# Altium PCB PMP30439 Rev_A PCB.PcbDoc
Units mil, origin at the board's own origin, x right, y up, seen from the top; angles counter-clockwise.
Board outline 2150 x 1400 mil, 2 copper layers (Top Layer, Bottom Layer), stack 62 mil thick; 24 components, 11 nets, 49 pads, 20 vias.
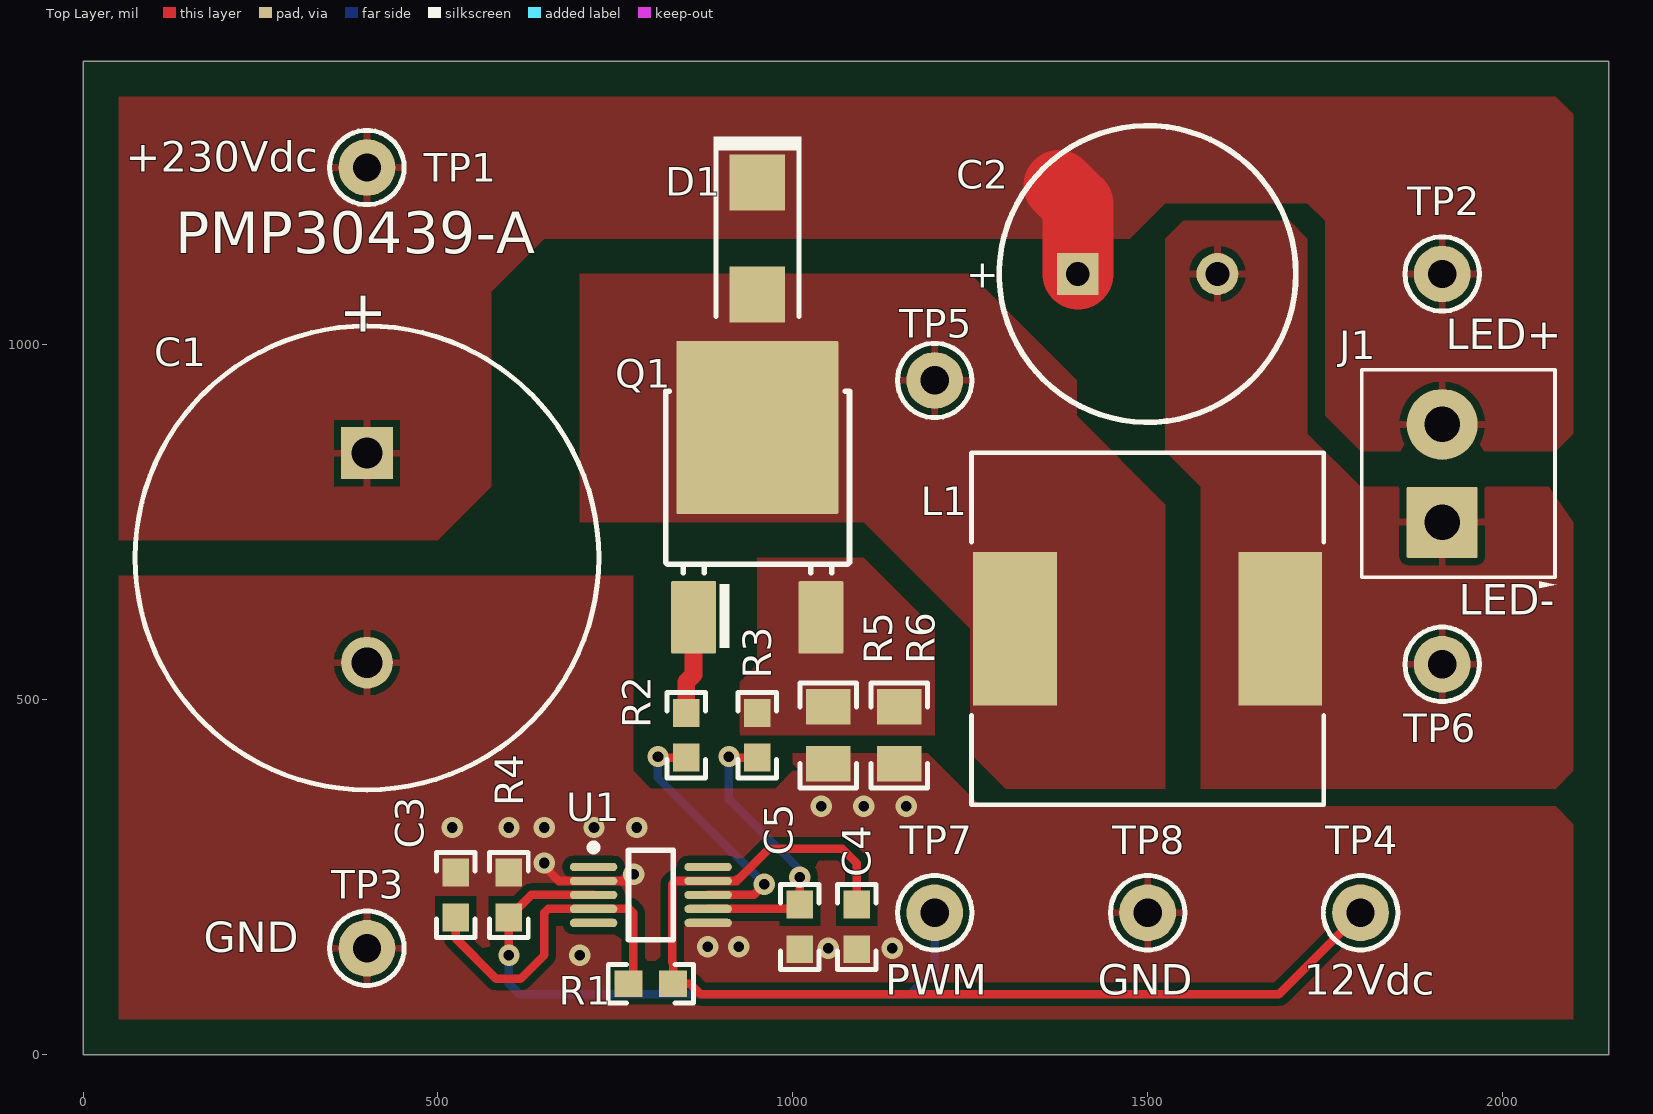
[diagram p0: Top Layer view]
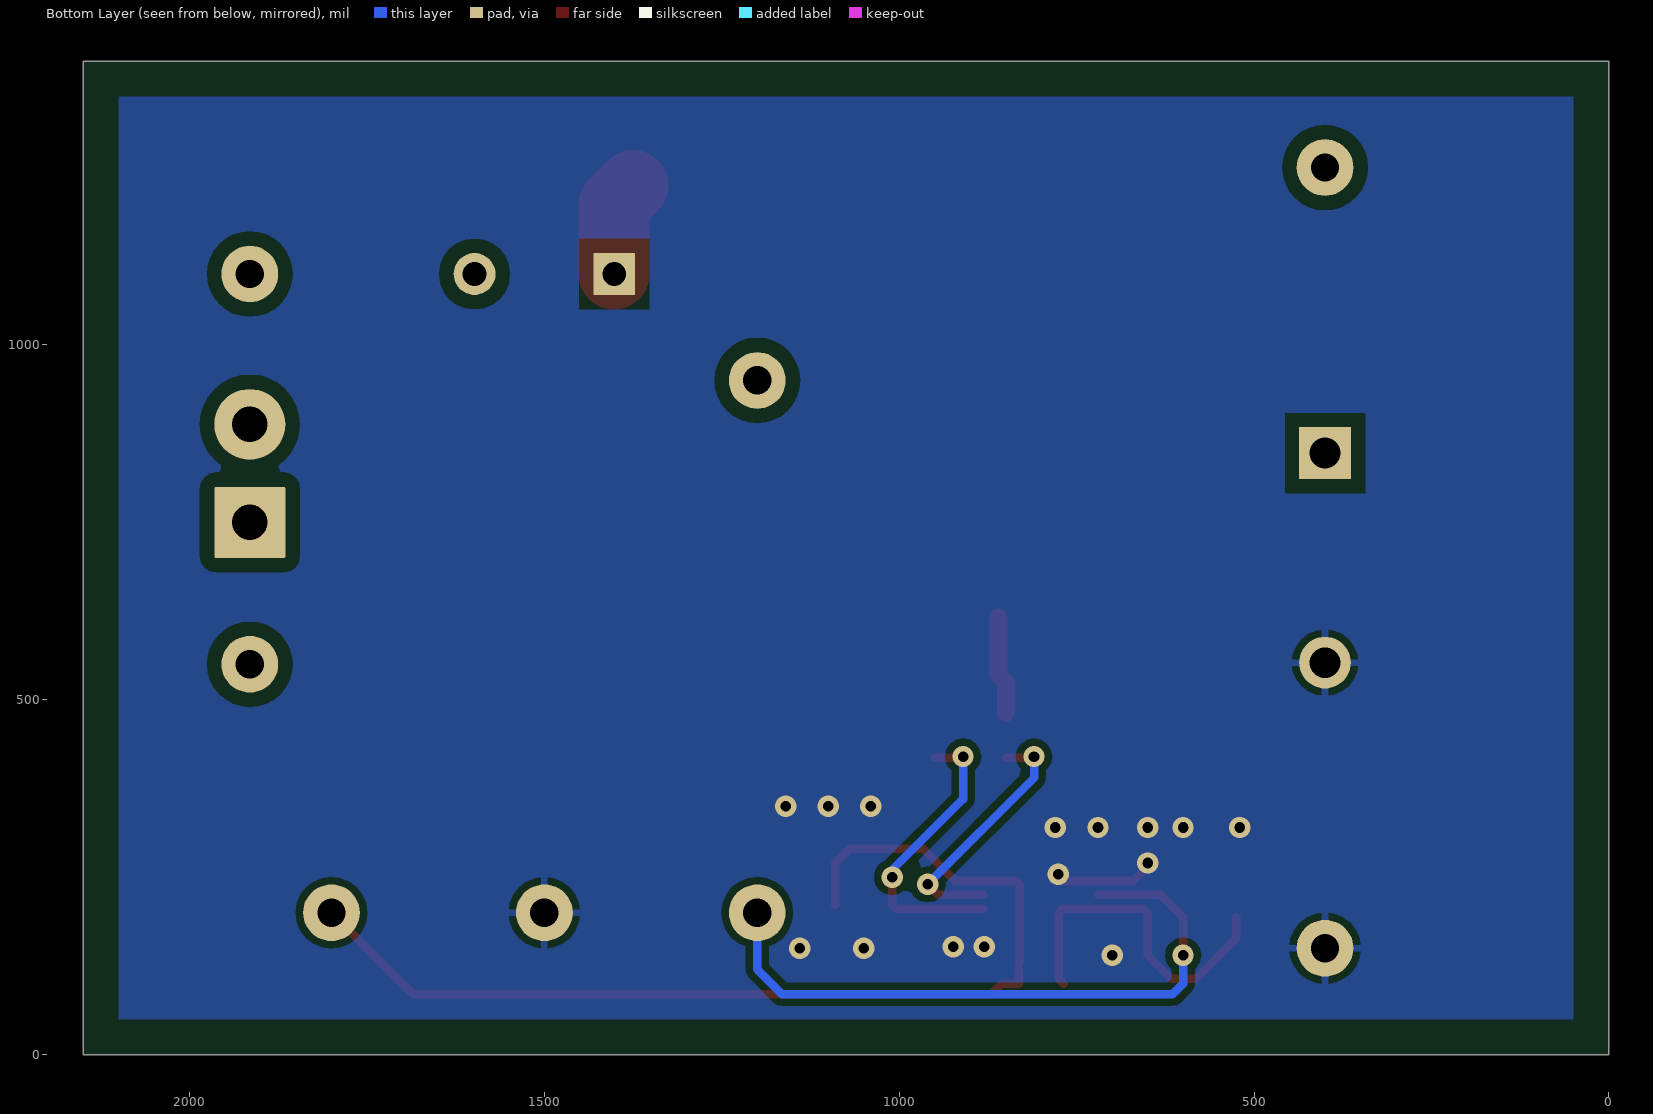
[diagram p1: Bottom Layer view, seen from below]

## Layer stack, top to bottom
Top Solder: solder mask 0.4, Solder Resist, Dk 3.5
Top Layer: signal copper 1.4
Dielectric1: core 59.2, FR-4, Dk 4.8
Bottom Layer: signal copper 1.4
Bottom Solder: solder mask 0.4, Solder Resist, Dk 3.5

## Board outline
0,0 0,1400 2150,1400 2150,0

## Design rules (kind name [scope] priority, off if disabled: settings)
AcuteAngle [All] p1: minimum=4.50000000000000E+0001 checktracksonly=FALSE
AssemblyTestPointUsage [All] p1: valid=2
BoardOutlineClearance BoardOutlineClearance_MountingHoles [OnCopper and InComponentClass('Mounting Holes')] p1: gap=40 ignorepadtopadclearanceinfootprint=FALSE
BoardOutlineClearance BoardOutlineClearance_Poly [OnCopper and IsPoly] p2: gap=25 ignorepadtopadclearanceinfootprint=FALSE
BoardOutlineClearance [OnCopper and Not InComponentClass('Logo') and not InComponentClass('FiducialMark') and not InRegion(1000,500,4000,800) and not InPoly] p3: gap=75 ignorepadtopadclearanceinfootprint=FALSE
Clearance "Schematic Clearance Constraint_4" [InNet('NetC2_2')] p1: gap=20 ignorepadtopadclearanceinfootprint=FALSE
Clearance "Schematic Clearance Constraint_3" [InNet('NetD1_2')] p2: gap=20 ignorepadtopadclearanceinfootprint=FALSE
Clearance "Schematic Clearance Constraint" [InNet('NetC1_1')] p3: gap=20 ignorepadtopadclearanceinfootprint=FALSE
Clearance "Schematic Clearance Constraint_13" [InNet('NetC5_1')] p4: gap=10 ignorepadtopadclearanceinfootprint=FALSE except(0: Arc-Hole Track-Hole SMDPad-Hole THPad-Hole Via-Hole Fill-Hole Poly-Hole Region-Hole Text-Hole)
Clearance "Schematic Clearance Constraint_12" [InNet('NetQ1_1')] p5: gap=10 ignorepadtopadclearanceinfootprint=FALSE except(0: Arc-Hole Track-Hole SMDPad-Hole THPad-Hole Via-Hole Fill-Hole Poly-Hole Region-Hole Text-Hole)
Clearance "Schematic Clearance Constraint_11" [InNet('NetQ1_3')] p6: gap=10 ignorepadtopadclearanceinfootprint=FALSE except(0: Arc-Hole Track-Hole SMDPad-Hole THPad-Hole Via-Hole Fill-Hole Poly-Hole Region-Hole Text-Hole)
Clearance "Schematic Clearance Constraint_10" [InNet('NetR2_1')] p7: gap=10 ignorepadtopadclearanceinfootprint=FALSE except(0: Arc-Hole Track-Hole SMDPad-Hole THPad-Hole Via-Hole Fill-Hole Poly-Hole Region-Hole Text-Hole)
Clearance "Schematic Clearance Constraint_9" [InNet('NetR4_2')] p8: gap=10 ignorepadtopadclearanceinfootprint=FALSE except(0: Arc-Hole Track-Hole SMDPad-Hole THPad-Hole Via-Hole Fill-Hole Poly-Hole Region-Hole Text-Hole)
Clearance "Schematic Clearance Constraint_8" [InNet('NetU1_1')] p9: gap=10 ignorepadtopadclearanceinfootprint=FALSE except(0: Arc-Hole Track-Hole SMDPad-Hole THPad-Hole Via-Hole Fill-Hole Poly-Hole Region-Hole Text-Hole)
Clearance "Schematic Clearance Constraint_7" [InNet('NetU1_5')] p10: gap=10 ignorepadtopadclearanceinfootprint=FALSE except(0: Arc-Hole Track-Hole SMDPad-Hole THPad-Hole Via-Hole Fill-Hole Poly-Hole Region-Hole Text-Hole)
Clearance "Schematic Clearance Constraint_6" [InNet('NetU1_10')] p11: gap=10 ignorepadtopadclearanceinfootprint=FALSE except(0: Arc-Hole Track-Hole SMDPad-Hole THPad-Hole Via-Hole Fill-Hole Poly-Hole Region-Hole Text-Hole)
Clearance "Schematic Clearance Constraint_5" [InNet('GND')] p12: gap=10 ignorepadtopadclearanceinfootprint=FALSE except(0: Arc-Hole Track-Hole SMDPad-Hole THPad-Hole Via-Hole Fill-Hole Poly-Hole Region-Hole Text-Hole)
Clearance "Schematic Clearance Constraint_2" [InNet('NetC3_1')] p13: gap=10 ignorepadtopadclearanceinfootprint=FALSE
Clearance U1 [All vs InComponent('U1')] p14: gap=7 ignorepadtopadclearanceinfootprint=FALSE
Clearance "Schematic Clearance Constraint_1" [InNet('NetC4_1')] p15: gap=10 ignorepadtopadclearanceinfootprint=FALSE except(0: Arc-Hole Track-Hole SMDPad-Hole THPad-Hole Via-Hole Fill-Hole Poly-Hole Region-Hole Text-Hole)
Clearance Clearance_Keepouts [((IsTrack Or IsArc) And Not InPoly) And IsFree and IsKeepOut vs ((IsTrack Or IsArc) And Not InPoly) And IsFree and IsKeepOut] p16: gap=0 ignorepadtopadclearanceinfootprint=FALSE
Clearance Clearance_Poly [InPolygon] p17: gap=25 ignorepadtopadclearanceinfootprint=FALSE except(0: Arc-Hole Track-Hole SMDPad-Hole THPad-Hole Via-Hole Fill-Hole Poly-Hole Region-Hole Text-Hole)
Clearance Clearance_FiducialMark [IsKeepOut and InComponentClass('FiducialMark') vs IsPad and InComponentClass('FiducialMark')] p18: gap=0 ignorepadtopadclearanceinfootprint=FALSE
Clearance [All] p19: gap=10 ignorepadtopadclearanceinfootprint=FALSE
ComponentClearance ComponentClearance_MountingHoles_FiducialMarks [InComponentClass('Mounting Holes') vs InComponentClass('FiducialMark')] p1: gap=50 collisioncheckmode=3 verticalgap=10 showdistances=FALSE
ComponentClearance ComponentClearance_Shunt [InComponentClass('Header') vs InComponentClass('Shunt')] p2: gap=0 collisioncheckmode=3 verticalgap=0 showdistances=FALSE
ComponentClearance ComponentClearance_Logo [InComponentClass('Logo')] p3: gap=50 collisioncheckmode=3 verticalgap=10 showdistances=FALSE
ComponentClearance ComponentClearance_ScrewToNut [(HasFootprint('NY PMS 440 0025 PH')) vs (HasFootprint('Keystone_1902C'))] p4: gap=5 collisioncheckmode=3 verticalgap=10 showdistances=FALSE
ComponentClearance ComponentClearance_MountingHoles [InComponentClass('Mounting Holes')] p5: gap=250 collisioncheckmode=3 verticalgap=100000 showdistances=FALSE
ComponentClearance ComponentClearance_SmallPassives [HasFootprint('0201*') or HasFootprint('0402*') or HasFootprint('0508') or HasFootprint('0603*') or HasFootprint('0612') or HasFootprint('0805*') or HasFootprint('0815*') or HasFootprint('0830*') or HasFootprint('1206*') or HasFootprint('1210*') or HasFootprint('1808*') or HasFootprint('1812*') or HasFootprint('1825*') or HasFootprint('2010*') or HasFootprint('2220*') or HasFootprint('2225*') or HasFootprint('2512*') or HasFootprint('2728*') or HasFootprint('3518*') vs HasFootprint('0201*') or HasFootprint('0402*') or HasFootprint('0508') or HasFootprint('0603*') or HasFootprint('0612') or HasFootprint('0805*') or HasFootprint('0815*') or HasFootprint('0830*') or HasFootprint('1206*') or HasFootprint('1210*') or HasFootprint('1808*') or HasFootprint('1812*') or HasFootprint('1825*') or HasFootprint('2010*') or HasFootprint('2220*') or HasFootprint('2225*') or HasFootprint('2512*') or HasFootprint('2728*') or HasFootprint('3518*')] p6: gap=14.96 collisioncheckmode=3 verticalgap=10 showdistances=FALSE
ComponentClearance ComponentClearance_THtoSMT [IsThruComponent vs IsSMTComponent] p7: gap=40 collisioncheckmode=3 verticalgap=30 showdistances=FALSE
ComponentClearance ComponentClearance_THtoTH [IsThruComponent vs IsThruComponent] p8: gap=30 collisioncheckmode=3 verticalgap=30 showdistances=FALSE
ComponentClearance [All] p9: gap=30 collisioncheckmode=3 verticalgap=10 showdistances=FALSE
DiffPairsRouting [All] p1: maxlimit=100 minlimit=10 mostfreqgap=10 toplayer_minwidth=15 toplayer_maxwidth=15 toplayer_prefwidth=15 bottomlayer_minwidth=15 bottomlayer_maxwidth=15 bottomlayer_prefwidth=15 maxuncoupledlength=1000
FabricationTestPointUsage TestPointUsage [All] p1: valid=2 allowmultiple=FALSE
FabricationTestpoint Testpoint [All] p1: side=3 testpointundercomponent=TRUE minsize=40 maxsize=100 preferedsize=60 minholesize=0 maxholesize=40 preferedholesize=32 testpointgrid=1 allowsidetop=TRUE allowsidebottom=TRUE usegrid=TRUE gridtolerance=0.01
FanoutControl Fanout_LCC [IsLCC] p1: bgadir=Out bgaviamode=Centered fanoutstyle=Auto fanoutdirection=Alternating viagrid=1 // Fanout_LCC (Default Rule)
FanoutControl Fanout_BGA [IsBGA] p2: bgadir=Out bgaviamode=Centered fanoutstyle=Auto fanoutdirection=Alternating viagrid=1 // Fanout_BGA (Default Rule)
FanoutControl Fanout_Default [All] p4: bgadir=Out bgaviamode=Centered fanoutstyle=Auto fanoutdirection=Alternating viagrid=1 // Fanout_Default (Default Rule)
FanoutControl Fanout_Small [(CompPinCount < 5)] p5: bgadir=Out bgaviamode=Centered fanoutstyle=Auto fanoutdirection=OutThenIn viagrid=1 // Fanout_Small (Default Rule)
HoleSize [All] p1: absolutevalues=TRUE maxlimit=251 minlimit=7.87 maxpercent=80.000 minpercent=20.000
MinimumAnnularRing MinimumAnnularRing_ThermalPadVias [IsVia and InAnyComponent] p1: minimumring=5.91
MinimumAnnularRing [All] p2: minimumring=8
MinimumSolderMaskSliver MinimumSolderMaskSliver_Logo [InComponentClass('Logo') vs InComponentClass('Logo')] p1: minsoldermaskwidth=0.7
MinimumSolderMaskSliver [All] p2: minsoldermaskwidth=3.94
PlaneConnect [All] p1: planeconnectstyle=Relief reliefexpansion=10 reliefentries=4 reliefconductorwidth=10 reliefairgap=10
PolygonConnect [All] p1: thpad.connectstyle=Relief thpad.reliefconductorwidth=10 thpad.reliefentries=4 thpad.polygonreliefangle="90 Angle" thpad.airgapwidth=10 smdpad.connectstyle=Direct smdpad.reliefconductorwidth=10 smdpad.reliefentries=4 smdpad.polygonreliefangle="90 Angle" smdpad.airgapwidth=10 via.connectstyle=Direct via.reliefconductorwidth=10 via.reliefentries=4 via.polygonreliefangle="90 Angle" via.airgapwidth=10
RoomDefinition "PMP30439 Rev_A Schematic" [InComponentClass('PMP30439 Rev_A Schematic')] p1: confinementstyle=ConfineIn formatcopy=TRUE lockcomponents=FALSE outline 4988,56 10878,56 10878,816 4988,816
RoutingVias ThermalPadVias [IsVia and InAnyComponent] p1: holewidth=7.87 width=19.68 viastyle="Through Hole" minholewidth=7.87 minwidth=19.68 maxholewidth=12.99 maxwidth=23.62
RoutingVias [All] p2: holewidth=16 width=34 viastyle="Through Hole" minholewidth=7.87 minwidth=26 maxholewidth=40 maxwidth=65
SilkToBoardRegionClearance [Not ((IsComment or IsDesignator) And (Hide <> 'False')) and not InRegion(1000,500,4000,800)] p1:
SilkToSilkClearance SilkToSilkClearance_Pb-FreeLogo [(HasFootprint('Pb-Free_Overlay_Medium') OR HasFootprint('Pb-Free_Overlay_Small')) vs (HasFootprint('Pb-Free_Overlay_Medium') OR HasFootprint('Pb-Free_Overlay_Small'))] p1: silktosilkclearance=0
SilkToSilkClearance [All] p2: silktosilkclearance=4
SilkToSolderMaskClearance SilkToComponentPadClearance [(IsPad or IsFill or IsRegion) and InAnycomponent] p1: minsilkscreentomaskgap=5 clearancetoexposedcopper=TRUE
SilkToSolderMaskClearance "Silk to Solder Mask Opening" [All] p2: minsilkscreentomaskgap=4 clearancetoexposedcopper=FALSE
SolderMaskExpansion [All] p1: expansion=1.97
Width [All] p1: maxlimit=100 minlimit=6 preferedwidth=10 checkconnectedcopper=TRUE
15 further rules are at their usual default settings.

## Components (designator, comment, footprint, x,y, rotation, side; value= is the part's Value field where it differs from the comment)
C1 "400KXW100MEFC16X30" CAPPR750W80D1600H3000 400,700 r270 top value=100uF
C2 "200CFX10MEFC10X16" CFX_1000x1600 1500,1100 r0 top value=10uF
C3 "C0603C561J5GACTU" 0603 525,225 r90 top value=560pF
C4 "885012206052" 0603 1090,180 r270 top value=1uF
C5 "DNP" 0603 1010,180 r270 top
D1 "ES1G-13-F" SMA 950,1150 r270 top value=400V
J1 "ED555/2DS" TERM_BLK_ED555-2DS 1915,750 r90 top
L1 "MSS1210-825KE" MSS1210 1500,600 r0 top value=8.2mH
Q1 "TK4P50D" DPAK 950,750 r90 top
R1 "RC0603FR-07150KL" 0603 800,100 r0 top value=150k
R2 "RC0603FR-0710RL" 0603 850,450 r90 top value=10.0
R3 "RC0603FR-0710RL" 0603 950,450 r90 top value=10.0
R4 "RC0603FR-07150KL" 0603 600,225 r270 top value=150k
R5 "RC0805FR-073R01L" 0805_HV 1050,450 r90 top value=3.01
R6 "DNP" 0805_HV 1150,450 r90 top
TP1 "5000" Keystone5000 400,1250 r90 top
TP2 "5000" Keystone5000 1915,1100 r90 top
TP3 "5001" Keystone5001 400,150 r90 top
TP4 "5000" Keystone5000 1800,200 r90 top
TP5 "5003" Keystone5003 1200,950 r90 top
TP6 "5002" Keystone5002 1915,550 r90 top
TP7 "5003" Keystone5003 1200,200 r90 top
TP8 "5001" Keystone5001 1500,200 r90 top
U1 "LM3445MM" MUB10A_N 800,225 r0 top

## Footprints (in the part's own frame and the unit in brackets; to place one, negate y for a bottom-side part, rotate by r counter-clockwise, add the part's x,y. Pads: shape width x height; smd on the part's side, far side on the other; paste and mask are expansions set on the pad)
0603 [mm] "0603 from SM-752 data"
  rect 1x0.95 smd: 1(-0.8,0) 2(0.8,0)
  silkscreen extent -1.52,-0.69 1.52,0.69, body extent -0.87,-0.47 0.87,0.47, height 1
0805_HV [mil] "0805 with 30mil clearance between pads"
  rect 50x63 smd: 1(-40,0) 2(40,0)
  silkscreen extent -74,-40 74,40, body extent -43,-29 43,29, height 57
CAPPR750W80D1600H3000 [mm] "Capacitor, Electrolytic, Radial; Body 16 x 30 mm (Dia.xH typ); Pin Spacing 7.5 mm (typ)"
  rect 1.85x1.85 hole 1.1: 1(-3.75,0)
  round 1.85 hole 1.1: 2(3.75,0)
  silkscreen extent -8.3,-8.3 8.3,8.3, body extent -8.19,-8.24 8.23,8.24, height 32.01
CFX_1000x1600 [mm] "RUBYCON"
  rect 1.5x1.5 hole 0.85: 1(-2.5,0)
  round 1.5 hole 0.85: 2(2.5,0)
  silkscreen extent -5.3,-5.31 5.31,5.31, body extent -5.21,-5.24 5.24,5.24, height 18.01
DPAK [mm] "D-PAK, 3-Pads, Body 6.22x6.73mm (max), TO-252AA using nominal STEP model"
  rrect6% 2.6x1.6 smd: 1(-3.4,2.28) 3(-3.4,-2.28)
  rrect2% 6.2x5.8 smd paste-2.9: 4(3.4,0)
  silkscreen extent -4.5,-3.3 4.7,3.28, body extent -3.86,-3.29 5.84,3.29, height 2.48
Keystone5000 [mil] "For Keystone 500x miniature loop terminals"
  round 80 hole 40: 1(0,0)
  silkscreen extent -52,-52 52,52, body extent -49,-49 49,49, height 182
Keystone5001 [mil] "For Keystone 500x miniature loop terminals"
  round 80 hole 40: 1(0,0)
  silkscreen extent -52,-52 52,52, body extent -49,-49 49,49, height 182
Keystone5002 [mil] "For Keystone 500x miniature loop terminals"
  round 80 hole 40: 1(0,0)
  silkscreen extent -52,-52 52,52, body extent -49,-49 49,49, height 182
Keystone5003 [mil] "For Keystone 500x miniature loop terminals"
  round 80 hole 40: 1(0,0)
  silkscreen extent -52,-52 52,52, body extent -49,-49 49,49, height 182
MSS1210 [mm] "Coilcraft MSS1210 series"
  rect 3x5.5 smd: 1(-4.75,0) 2(4.75,0)
  silkscreen extent -6.3,-6.3 6.3,6.3, body extent -6.15,-6.15 6.15,6.15, height 10.2
MUB10A_N [mm] "TSSOP, 10-Leads, Body 3x3mm, Pitch 0.5mm, IPC Medium Density"
  oval 1.7x0.3 smd: 1(-2.05,1) 2(-2.05,0.5) 3(-2.05,0) 4(-2.05,-0.5) 5(-2.05,-1) 6(2.05,-1) 7(2.05,-0.5) 8(2.05,0) 9(2.05,0.5) 10(2.05,1)
  silkscreen extent -2.17,-1.6 0.8,1.82, body extent -1.6,-1.6 1.6,1.6, height 1.09
SMA [mm] "Molded Diode, 2-Leads, Body 4.3x2.6mm, IPC Medium Density, based on OnSemi component dimensions and land pattern"
  rect 2x2 smd: 1(-2,0) 2(2,0)
  silkscreen extent -3.66,-1.57 2.79,1.57, body extent -2.6,-1.3 2.6,1.3, height 2.42
TERM_BLK_ED555-2DS [mil]
  rrect4% 100x100 hole 50: 1(0,0)
  round 100 hole 50: 2(138,0)
  silkscreen extent -93,-161 215,113, body extent -69,-150 207,106, height 323

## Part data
C1: "CAP, AL, 100 µF, 400 V, +/- 20%, TH", Cap_Case="RCAP, 16x30mm", Manufacturer=Rubycon, Supplier Part Number 1=400KXW100MEFC16X30-ND, Tolerance_%=20, Value2=400V, ValueDisplayed=100µF
C2: "CAP, AL, 10 µF, 200 V, +/- 20%, TH", Cap_Case=10x16, Manufacturer=Rubycon, Supplier Part Number 1=200CFX10MEFC10X16-ND, Tolerance_%=20, Value2=200V, ValueDisplayed=10µF
C3: "CAP, CERM, 560 pF, 50 V,+/- 5%, C0G/NP0, 0603", Cap_Case=0603, Manufacturer=Kemet, Supplier Part Number 1=399-3287-1-ND, TempCo=C0G/NP0, Tolerance_%=5, Value2=50V, ValueDisplayed=560pF
C4: "CAP, CERM, 1 µF, 16 V,+/- 10%, X7R, 0603", Cap_Case=0603, Manufacturer="Wurth Elektronik", Supplier Part Number 1=710-885012206052, TempCo=X7R, Tolerance_%=10, Value2=16V, ValueDisplayed=1µF
C5: library part C0603C561J5GACTU, "CAP, CERM, DNP, 50 V,+/- 5%, C0G/NP0, 0603", Cap_Case=0603, Manufacturer=Kemet, TempCo=C0G/NP0, Tolerance_%=5, Value2=50V
D1: "Diode, Superfast Rectifier, 400 V, 1 A, SMA", Manufacturer="Diodes Inc.", Supplier Part Number 1=ES1G-FDICT-ND, Value1=1A, Value2=1.25V
J1: "Terminal Block, 3.5mm Pitch, 2x1, TH", Color=Grey, Current_A=6, Manufacturer="On-Shore Technology", Supplier Part Number 1=ED1514-ND, Voltage_V=150
L1: "Inductor, Shielded, Ferrite, 8.2 mH, 0.35 A, 6.2 ohm, SMD", Manufacturer=Coilcraft, Supplier Part Number 1=994-MSS1210-825KEB, Value1="6.2 ohm", Value2=0.35A, ValueDisplayed=8.2mH
Q1: library part FCD4N60TM, "MOSFET, N-CH, 500 V, 4 A, DPAK", Alternate Manufacturer=None, Manufacturer="Fairchild Semiconductor", Supplier Part Number 1=TK4P50D(T6RSS-Q)-ND, Value1="1.7 ohm", Value2="9 nC"
R1 R4: "RES, 150 k, 1%, 0.1 W, 0603", Manufacturer="Yageo America", Power_W=0.1, Supplier Part Number 1=311-150KHRCT-ND, TempCo="200 ppm/C", Tolerance_%=1, Value1=1%, Value2=0.1W, Value_Code=150k
R2 R3: "RES, 10.0, 1%, 0.1 W, 0603", Manufacturer="Yageo America", Power_W=0.1, Supplier Part Number 1=311-10.0HRCT-ND, TempCo="200 ppm/C", Tolerance_%=1, Value1=1%, Value2=0.1W, Value_Code=10R0, ValueDisplayed=10.0
R5: "RES, 3.01, 1%, 0.125 W, 0805", Manufacturer="Yageo America", Power_W=0.125, Supplier Part Number 1=311-3.01CRCT-ND, TempCo="200 ppm/C", Tolerance_%=1, Value1=1%, Value2=0.125W, Value_Code=3R01, ValueDisplayed=3.01
R6: library part RC0805FR-073R01L, "RES, DNP, 1%, 0.125 W, 0805", Manufacturer="Yageo America", Power_W=0.125, TempCo="200 ppm/C", Tolerance_%=1, Value1=1%, Value2=0.125W
TP1 TP2 TP4: "Test Point, Miniature, Red, TH", Color=Red, Manufacturer=Keystone, Supplier Part Number 1=36-5000-ND
TP3 TP8: "Test Point, Miniature, Black, TH", Color=Black, Manufacturer=Keystone, Supplier Part Number 1=36-5001-ND
TP5 TP7: "Test Point, Miniature, Orange, TH", Color=Orange, Manufacturer=Keystone, Supplier Part Number 1=36-5003-ND
TP6: "Test Point, Miniature, White, TH", Color=White, Manufacturer=Keystone, Supplier Part Number 1=36-5002-ND
U1: "Triac Dimmable Offline LED Driver, PowerWise, 10-pin MSOP", Manufacturer="Texas Instruments", PackageTopMarking=ZXTT*SULB, PowerWise=Y, Supplier Part Number 1=1699377

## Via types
v1: diameter 30, hole 15, Top Layer to Bottom Layer, 20 vias

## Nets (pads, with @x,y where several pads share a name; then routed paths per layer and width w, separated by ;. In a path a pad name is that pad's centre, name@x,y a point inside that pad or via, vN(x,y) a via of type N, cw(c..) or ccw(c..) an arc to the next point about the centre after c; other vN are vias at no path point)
GND: C1.2 C3.2 C4.2 C5.2 R4.1 R5.1 R6.1 TP3.1 TP8.1 U1.2 U1.6 | length 131.2
  Top Layer w12: v1@655,260 670.31,244.69 U1.2 766.69,244.69 v1(776,254)
  other v1: 700,140 1050,150 1140,150 880,152.17 924.02,152.17 650,270 520,320 600,320 650,320 720,320 780,320 1040,350 1100,350 1160,350
NetC1_1: C1.1 C2.1 D1.1 J1.2 TP1.1 TP2.1 | length 136
  Top Layer w100: 1375,1225 1401.57,1198.43 C2.1
NetC2_2: C2.2 J1.1 L1.2 TP6.1
NetC3_1: C3.1 R1.1 U1.4 | length 483.8
  Top Layer w12: C3.1 525,163.98 582.22,106.76 616.31,106.76 650,140.44 650,200 655.32,205.32 U1.4 769.68,205.32 775,200 775,106.5 R1.1
NetC4_1: C4.1 R1.2 TP4.1 U1.9 | length 1509.5
  Top Layer w12: 920.84,244.69 U1.9 834.69,244.69 830,240 830,130 831.5,128.5 R1.2 855,100 870,85 1685,85 TP4.1 ; 920.84,247 923.16,247 966.16,290 1070,290 1090,270 C4.1
NetC5_1: C5.1 R3.1 U1.7 | length 422.4
  Top Layer w12: U1.7 1003.82,205.32 C5.1 v1(1010,250) ; v1(910,420) 911.5,418.5 R3.1
  Bottom Layer w12: v1(910,420) 910,360 1010,260 v1(1010,250)
NetD1_2: D1.2 L1.1 Q1.4 TP5.1
NetQ1_1: Q1.1 R2.2 | length 138.9
  Top Layer w25: R2.2 850,525 860.24,535.24 Q1.1
NetQ1_3: Q1.3 R3.2 R5.2 R6.2
NetR2_1: R2.1 U1.8 | length 368.3
  Top Layer w12: v1(810,420) 811.5,418.5 R2.1 ; U1.8 945,225 v1(960,240)
  Bottom Layer w12: v1(810,420) 810,390 v1(960,240)
NetR4_2: R4.2 TP7.1 U1.3 | length 926.6
  Top Layer w12: v1(600,140) R4.2 631.5,225 U1.3
  Bottom Layer w12: v1(600,140) 600,100 615,85 1165,85 1200,120 TP7.1
pads on no net: U1.1 U1.5 U1.10

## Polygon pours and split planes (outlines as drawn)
NetC1_1 on Top Layer "TOP_LAYER_NETC1_1_P002" (solid, remove dead copper, pour order 2): 50,1350 2075,1350 2100,1325 2100,875 2075,850 1800,850 1750,900 1750,1175 1725,1200 1525,1200 1500,1175 1475,1150 1200,1150 650,1150 575,1075 575,800 500,725 50,725
NetD1_2 on Top Layer "TOP_LAYER_NETD1_2_P004" (solid, remove dead copper, pour order 4): 700,1100 1250,1100 1400,950 1400,900 1525,775 1525,375 1300,375 1250,425 1250,600 1100,750 700,750
NetC2_2 on Top Layer "TOP_LAYER_NETC2_2_P006" (solid, remove dead copper, pour order 6): 1525,1150 1550,1175 1700,1175 1725,1150 1725,875 1800,800 2065,800 2100,750 2100,400 2075,375 1575,375 1575,800 1525,850
NetQ1_3 on Top Layer "TOP_LAYER_NETQ1_3_P008" (solid, remove dead copper, pour order 8): 950,700 1100,700 1200,600 1200,450 921.46,450 925,453.54 925,525 950,550
GND on Top Layer "TOP_LAYER_GND_P010" (solid, remove dead copper, pour order 10): 50,675 775,675 775,400 800,375 975,375 1000,400 1010,400 1000,410 1000,425 1190,425 1265,350 2075,350 2100,325 2100,50 50,50
GND on Bottom Layer "BOTTOM_LAYER_GND_P012" (solid, remove dead copper, pour order 12): 50,1350 2100,1350 2100,50 50,50

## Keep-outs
Keep-Out Layer:
  text ".Layer_Name" at 577,-858.49 h60

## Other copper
Top Layer:
  text ".Layer_Name" at 577,-858.49 h60
Bottom Layer:
  text ".Layer_Name" at 577,-858.49 h60

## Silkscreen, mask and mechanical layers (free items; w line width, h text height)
Top Overlay:
  text "+230Vdc" at 60,1230 h72.83
  text "PMP30439-A" at 130,1110 h100
  text "LED+" at 1920,980 h72.83
  text "LED-" at 1938.07,605.7 h72.83
  text "GND" at 170,130 h72.83
  text "PWM" at 1130,70 h72.83
  text "GND" at 1430,70 h72.83
  text "12Vdc" at 1720,70 h72.83
  text ".Layer_Name" at 577,-858.49 h60
Bottom Overlay:
  text ".Layer_Name" at 577,-858.49 h60
Top Paste:
  text ".Layer_Name" at 577,-858.49 h60
Bottom Paste:
  text ".Layer_Name" at 577,-858.49 h60
Top Solder:
  text ".Layer_Name" at 577,-858.49 h60
  text ".Layer_Name" at 577,-858.49 h60
Bottom Solder:
  text "'.PRJ_Number'.PCB_Rev-" at 650,1110 h108.27
  text ".Layer_Name" at 577,-858.49 h60
Drill Guide:
  text ".Layer_Name" at 577,-858.49 h60
M1 Board Outline:
  the board outline again, w10
  text ".Layer_Name" at 577,-858.49 h60
M2 Board Dimensions:
  rectangle: 125,-400 500,-275
  rectangle: 0,-275 125,-150
  lines w7: 0,-275 1000,-275 ; 125,-400 125,-150 ; 250,-400 250,-150 ; 500,-400 500,-150 ; 750,-400 750,-150 ; 0,-400 0,-150 1000,-150 1000,-400 0,-400
  text ".Layer_Name" at 577,-858.49 h60
M3 3D STEP Top:
  text ".Layer_Name" at 577,-858.49 h60
M4 3D STEP Bottom:
  text ".Layer_Name" at 577,-858.49 h60
M5 Assembly Top:
  lines w10: -292,-930.17 6308,-930.17 ; -292,-726.83 6310,-726.83 ; -292,-523.5 -292,-1133.5 3713,-1133.5 6310,-1133.5 6310,-523.5 -291.5,-523.5 -291.5,-1133.5 1284,-1133.5 ; 2173,-1133.5 2173,-523.5 ; 3440,-726.83 3440,-523.5 ; 4280,-726.83 4280,-523.5 ; 4902,-1140 4902,-937.17
  text "COMPONENTS MARKED 'DNP' SHOULD NOT BE POPULATED." at 1153.5,-318.5 h60
  text "ASSEMBLY VARIANT:" at 1153,-434 h60
  text ".VariantName" at 2189,-434 h60
  text "PCB VIEWED FROM TOP SIDE" at -228.5,-655.67 h60
  text "BOARD #:" at 2248,-655.67 h60
  text ".PRJ_Number" at 2793.5,-655.67 h60
  text "REV:" at 3638,-655.67 h60
  text ".PCB_Rev" at 3929.5,-655.67 h60
  text "SVN REV:" at 4476,-655.67 h60
  text ".VersionControl_RevNumber" at 4982,-655.67 h60
  text "TID #:" at 2248,-859 h60
  text ".TID" at 2793.5,-859 h60
  text "PLOT NAME =" at -228.5,-1064.34 h60
  text ".plot_File_Name" at 577,-1064.34 h60
  text "GENERATED    :" at 2250,-1064.34 h60
  text ".Print_Date" at 3119.5,-1064.34 h60
  text ".Print_Time" at 3848.5,-1064.34 h60
  text "TEXAS INSTRUMENTS" at 5113,-1064.34 h60
M6 Assembly Bottom:
  lines w10: -292.5,-727.33 6309.5,-727.33 ; -290.5,-930.67 6309.5,-930.67 ; 1115.5,-1140.5 1115.5,-937.67 ; 1737.5,-727.33 1737.5,-524 ; 2577.5,-727.33 2577.5,-524 ; 3844.5,-1134 3844.5,-524 ; 4733.5,-1134 6309,-1134 6309,-524 -292.5,-524 -292.5,-1134 2304.5,-1134 6309.5,-1134 6309.5,-524
  text "COMPONENTS MARKED 'DNP' SHOULD NOT BE POPULATED." at 6102,-318 h60
  text ".VariantName" at 5058,-434 h60
  text "ASSEMBLY VARIANT:" at 6097,-434 h60
  text ".VersionControl_RevNumber" at 1035.5,-656.17 h60
  text "SVN REV:" at 1541.5,-656.17 h60
  text ".PCB_Rev" at 2088,-656.17 h60
  text "REV:" at 2379.5,-656.17 h60
  text ".PRJ_Number" at 3224,-656.17 h60
  text "BOARD #:" at 3769.5,-656.17 h60
  text "PCB VIEWED FROM BOTTOM SIDE" at 6246,-656.17 h60
  text ".TID" at 3224,-859.5 h60
  text "TID #:" at 3769.5,-859.5 h60
  text "TEXAS INSTRUMENTS" at 904.5,-1064.84 h60
  text ".Print_Time" at 2169,-1064.84 h60
  text ".Print_Date" at 2898,-1064.84 h60
  text "GENERATED    :" at 3767.5,-1064.84 h60
  text ".plot_File_Name" at 5440.5,-1064.84 h60
  text "PLOT NAME =" at 6246,-1064.84 h60
M9 Title Sheet:
  drawing of 57 lines, arcs and shapes, not listed
  text "1" at 739.84,8036.5 h70
  text "2" at 3235.5,8036.5 h70
  text "3" at 5724.84,8036.5 h70
  text "4" at 8231.51,8036.5 h70
  text "5" at 10730.5,8036.5 h70
  text "6" at 13235.5,8036.5 h70
  text "A" at -416.5,6893.5 h70
  text "A" at 14383.5,6893.5 h70
  text "B" at -416.5,4513.5 h70
  text "B" at 14383.5,4513.5 h70
  text "C" at -416.5,2138.5 h70
  text "C" at 14383.5,2138.5 h70
  text "PROJECT TITLE:" at 11343.5,277.5 h45
  text ".PRJ_Title" at 11393.5,144.17 h70
  text "DESIGNED FOR:" at 11343.5,-23.5 h45
  text ".PRJ_Customer" at 11393.5,-163.5 h70
  text "D" at -416.5,-231.5 h70
  text "D" at 14383.5,-231.5 h70
  text "FILE NAME:" at 11343.5,-323.5 h45
  text ".PCB_File_Name_No_Path" at 11393.5,-443.5 h70
  text "Texas Instruments (TI) and/or its licensors do not warrant the accuracy or completeness of this specification" at 6374,-605.34 h45
  text "ENGINEER:" at 11343.5,-613.5 h45
  text "LAYOUT BY:" at 12848.5,-613.5 h45
  text "or any information contained therein. TI and/or its licensors do not warrant that this design will meet" at 6329.01,-718 h45
  text ".PRJ_Engineer" at 11393.5,-768.49 h70
  text ".PCB_Layout" at 12899,-768.49 h70
  text "the specifications, will be suitable for your application or fit for any particular purpose, or will operate in" at 6329.01,-830.67 h45
  text ".Layer_Name" at 577,-858.49 h60
  text "ALTIUM DESIGNER VERSION:" at 12848.5,-923.5 h45
  text "an implementation. TI and/or its licensors do not warrant that the design is production worthy. You should" at 6329.01,-943.33 h45
  text "completely validate and test your design implementation to confirm the system functionality for your application." at 6374,-1056 h45
  text ".print_Scale" at 11393.5,-1056.83 h70
  text ".Application_BuildNumber" at 12899,-1056.83 h70
  text "1" at 739.84,-1263.5 h70
  text "2" at 3235.5,-1263.5 h70
  text "3" at 5724.84,-1263.5 h70
  text "4" at 8231.51,-1263.5 h70
  text "5" at 10730.5,-1263.5 h70
  text "6" at 13235.5,-1263.5 h70
M10 Fab Notes:
  drawing of 189 lines, arcs and shapes, not listed
  text "DESIGN INFORMATION" at 12382.02,6356.17 h60
  text "MIN. TRACK WIDTH:" at 11737.46,6224.05 h60
  text "8" at 12833.7,6224.05 h60
  text "MIL" at 12988.46,6224.05 h60
  text "MIN. CLEARANCE:" at 11737.46,6099.92 h60
  text "0.2" at 12773.7,6099.93 h60
  text "mm" at 12988.46,6099.92 h60
  text "MIN. VIA PAD SIZE:" at 11737.46,5975.8 h60
  text "24" at 12803.71,5975.8 h60
  text "MIL" at 12988.46,5975.8 h60
  text "0.05mm (2MIL)" at 12432.46,5845.9 h60
  text "MINIMUM ANNULAR RING" at 11408.23,5837.67 h60
  text "EXTERNAL" at 13140.46,5837.67 h60
  text "PER" at 11608.23,5727.55 h60
  text "IPC-D-275 CLASS 2 LEVEL C" at 11828.23,5727.54 h60
  text "MIL, HOLES" at 13316.46,5627.07 h60
  text "+/-" at 12924,5618.48 h60
  text "+/-" at 13778,5618.48 h60
  text "REGISTRATION TOLERANCES:" at 11408.23,5617.42 h60
  text "METAL" at 12608,5617.42 h60
  text "5" at 13184.2,5617.42 h60
  text "3" at 14017.2,5617.42 h60
  text "MIL" at 14133.46,5617.42 h60
  text "HOLE SIZE TOLERANCE (UNLESS OTHERWISE SPECIFIED):" at 11408.23,5519.1 h60
  text "+/-" at 13778,5516.23 h60
  text "3" at 14017.2,5515.17 h60
  text "MIL" at 14133.46,5515.17 h60
  text "MATERIAL:" at 11333.46,5377.52 h60
  text "FR-4 High Tg" at 12319.9,5249 h60
  text "X" at 12175.46,5241.01 h60
  text "FR-408" at 11754.46,5236.49 h60
  text "OTHER" at 13242.46,5236.49 h60
  text "62 MIL (1.6mm) +/-10%" at 12074.56,5093.46 h60
  text "X" at 11954.46,5091.01 h60
  text "THICKNESS:" at 11408.23,5085.24 h60
  text "OTHER" at 13359.46,5085.24 h60
  text "TOLERANCE:" at 11408.23,4946.92 h60
  text "X" at 12256.46,4946.92 h60
  text "ANSI IPC-6012 TYPE 3 CLASS 2" at 12434.48,4946.92 h60
  text "OTHER +/-" at 12434.46,4802.73 h60
  text "BOW & TWIST:" at 11408.23,4657.54 h60
  text "X" at 12256.46,4657.54 h60
  text "ANSI IPC-6012 TYPE 3 CLASS 2" at 12434.48,4657.54 h60
  text "OTHER +/-" at 12434.46,4510.85 h60
  text "DRILLING:" at 11333.46,4380.23 h60
  text "NC_DRILL FILES" at 13094.46,4275.04 h60
  text "REFERENCE:" at 11408.23,4271.1 h60
  text "X" at 12065.46,4271.01 h60
  text "AS SHOWN" at 12243.46,4271.1 h60
  text "X" at 12966.46,4271.1 h60
  text "OTHER" at 13392.46,4128.85 h60
  text "PTH COPPER THICKNESS:" at 11407.91,4125.32 h60
  text "X" at 12547.14,4125.32 h60
  text "20-30 um" at 12675.14,4125.32 h60
  text "BOARD FINISH:" at 11333.46,3977.73 h60
  text "SILKSCREEN:" at 11488.68,3867.6 h60
  text "X" at 12446.46,3867.6 h60
  text "TOP" at 12563.46,3867.6 h60
  text "X" at 12956.46,3867.6 h60
  text "BOTTOM" at 13074.46,3867.6 h60
  text "SILKSCREEN COLOR:" at 11488.68,3712.41 h60
  text "X" at 12445.46,3712.41 h60
  text "WHITE" at 12563.46,3712.41 h60
  text "OTHER" at 13074.46,3712.41 h60
  text "X" at 12576.46,3568.96 h60
  text "GREEN" at 12694.46,3568.96 h60
  text "OTHER" at 13312.46,3568.96 h60
  text "SOLDER RESIST COLOR:" at 11488.68,3562.1 h60
  text "X" at 12576.46,3414.71 h60
  text "MATTE" at 12694.46,3414.71 h60
  text "SEMI-GLOSS" at 13312,3414.07 h60
  text "IMMERSION GOLD (ENIG)" at 12394.46,3241.94 h60
  text "ENEPIG" at 13732,3234.72 h60
  text "SURFACE FINISH:" at 11333.46,3233.72 h60
  text "X" at 12216.46,3233.72 h60
  text "IMM. TIN/SILVER OR EQUIV" at 11663,3096.4 h60
  text "OTHER" at 13094.46,3092.47 h60
  text "ARRAY/PANEL:" at 11333.46,2937.09 h60
  text "CUT AND TRIM PER M1 BOARD OUTLINE" at 12394.46,2928.87 h60
  text "N.C. ROUTE" at 12394.46,2792.9 h60
  text "X" at 13082.46,2792.9 h60
  text "V. SCORE" at 13260.46,2792.9 h60
  text "CERTIFICATION:" at 11333.46,2663.77 h60
  text "MATERIALS AND WORKMANSHIP FOR ALL PCBS" at 12058.46,2663.77 h60
  text "TO MEET OR EXCEED THE REQUIREMENTS OF:" at 12058.46,2569.71 h60
  text "X" at 11695.97,2441.08 h60
  text "ANSI IPC-A-600F CLASS ->" at 11823.96,2441.08 h60
  text "X" at 13471.97,2441.08 h60
  text "2" at 13581.96,2441.08 h60
  text "1" at 13266.96,2439.58 h60
  text "3" at 13935.96,2439.58 h60
  text "X" at 12507.97,2293.39 h60
  text "RoHS" at 12635.96,2293.39 h60
  text "OTHER" at 13280.36,2293.39 h60
  text "PER ORDER" at 13677.42,2293.39 h60
  text "ALL BOARDS MUST MEET OR EXCEED UL94-V0 REQUIREMENTS." at 11361,2139.57 h60
  text "PCB MUST BEAR THE UL94V-0 UL REGISTERED MATERIAL ID NUMBER" at 11361,2023.5 h60
  text "ADDITIONAL REQUIREMENTS:" at 11333.46,1854.08 h60
  text "MICROSECTION:" at 11408.23,1746.95 h60
  text "YES" at 12313.96,1746.95 h60
  text "REQUIRED" at 13175.46,1602.62 h60
  text "BARE BOARD ELEC. TEST:" at 11408.23,1599.76 h60
  text "NONE" at 12713.96,1599.76 h60
  text "X" at 13057.46,1599.76 h60
  text "PER ORDER" at 13767.46,1599.76 h60
  text "XX MIL VIAS REQUIRE NON-CONDUCTIVE FILL AND PLANARIZE" at 11576.38,1394.82 h59
  text "XX MIL VIAS REQUIRE CONDUCTIVE FILL AND PLANARIZE" at 11584.38,1290.84 h60
  text "OUTER XX MIL VIAS REQUIRE 50 OHM SINGLE-ENDED IMPEDANCE" at 11583.39,1127.46 h58
  text "LAYER 2 & 3 (INNER LAYERS) XX MIL WIDE, XX MIL SPACE / TRACES REQUIRE 100 OHM DIFFERENTIAL IMPEDANCE" at 11575.39,891.74 h60
  text ".Layer_Name" at 577,-858.49 h60
M11 Gerber Information:
  lines w10: -292,-930.17 6308,-930.17 ; -292,-726.83 6310,-726.83 ; -292,-523.5 -292,-1133.5 3713,-1133.5 6310,-1133.5 6310,-523.5 -291.5,-523.5 -291.5,-1133.5 1284,-1133.5 ; 2173,-1133.5 2173,-523.5 ; 3440,-726.83 3440,-523.5 ; 4280,-726.83 4280,-523.5 ; 4902,-1140 4902,-937.17
  text "ALL ARTWORK VIEWED FROM TOP SIDE" at -228.5,-655.67 h60
  text "BOARD #:" at 2248,-655.67 h60
  text ".PRJ_Number" at 2793.5,-655.67 h60
  text "REV:" at 3638,-655.67 h60
  text ".PCB_Rev" at 3929.5,-655.67 h60
  text "SVN REV:" at 4476,-655.67 h60
  text ".VersionControl_RevNumber" at 4982,-655.67 h60
  text "LAYER NAME =" at -228.5,-858.49 h60
  text "TID #:" at 2248,-859 h60
  text ".TID" at 2793.5,-859 h60
  text "PLOT NAME =" at -228.5,-1064.34 h60
  text ".plot_File_Name" at 577,-1064.34 h60
  text "GENERATED    :" at 2250,-1064.34 h60
  text ".Print_Date" at 3119.5,-1064.34 h60
  text ".Print_Time" at 3848.5,-1064.34 h60
  text "TEXAS INSTRUMENTS" at 5113,-1064.34 h60
M12 Stackup:
  drawing of 191 lines, arcs and shapes, not listed
  text "Layer" at 9790.34,7830 h60
  text "Name" at 10200.26,7830 h60
  text "Material" at 11130,7830 h60
  text "Thickness" at 11989.77,7830 h60
  text "Constant" at 12639.6,7830 h60
  text "Board Layer Stack" at 13209.46,7830 h60
  text "1" at 9790.34,7710 h60
  text "Top Overlay" at 10200.26,7710 h60
  text "2" at 9790.34,7590 h60
  text "Top Solder" at 10200.26,7590 h60
  text "Solder Resist" at 11130,7590 h60
  text "0.40mil" at 11989.77,7590 h60
  text "3.5" at 12639.6,7590 h60
  text "3" at 9790.34,7470 h60
  text "Top Layer" at 10200.26,7470 h60
  text "Copper" at 11130,7470 h60
  text "1.40mil" at 11989.77,7470 h60
  text "4" at 9790.34,7350 h60
  text "Dielectric1" at 10200.26,7350 h60
  text "FR-4" at 11130,7350 h60
  text "59.20mil" at 11989.77,7350 h60
  text "4.8" at 12639.6,7350 h60
  text "5" at 9790.34,7230 h60
  text "Bottom Layer" at 10200.26,7230 h60
  text "Copper" at 11130,7230 h60
  text "1.40mil" at 11989.77,7230 h60
  text "6" at 9790.34,7110 h60
  text "Bottom Solder" at 10200.26,7110 h60
  text "Solder Resist" at 11130,7110 h60
  text "0.40mil" at 11989.77,7110 h60
  text "3.5" at 12639.6,7110 h60
  text "7" at 9790.34,6990 h60
  text "Bottom Overlay" at 10200.26,6990 h60
  text ".Layer_Name" at 577,-858.49 h60
M13 Component Bodies Top:
  text ".Layer_Name" at 577,-858.49 h60
M14 Component Bodies Bottom:
  text ".Layer_Name" at 577,-858.49 h60
M15 Courtyards Top:
  text ".Layer_Name" at 577,-858.49 h60
M16 Courtyards Bottom:
  text ".Layer_Name" at 577,-858.49 h60
Drill Drawing:
  lines w10: 5336.09,2755.19 5349.9,2755.19 5363.72,2741.38 5377.53,2755.19 5391.34,2755.19 5377.53,2769 5391.34,2782.82 5377.53,2782.82 5363.72,2796.63 5349.9,2782.82 5336.09,2782.82 5349.9,2769 5336.09,2755.19 ; 5336.09,2920.95 5391.34,2920.95 5363.72,2865.7 5336.09,2920.95 ; 5336.09,2990.02 5391.34,2990.02 5391.34,3045.27 5336.09,3045.27 5336.09,2990.02 ; 5336.09,3114.34 5363.72,3128.15 5391.34,3114.34 5377.53,3141.96 5391.34,3169.59 5363.72,3155.78 5336.09,3169.59 5349.9,3141.96 5336.09,3114.34 ; 5336.09,3252.47 5349.9,3252.47 5349.9,3238.66 5377.53,3238.66 5377.53,3252.47 5391.34,3252.47 5391.34,3280.1 5377.53,3280.1 5377.53,3293.91 5349.9,3293.91 5349.9,3280.1 5336.09,3280.1 5336.09,3252.47
  lines w12: 5286,2704.08 8517.49,2704.08 ; 5286,3325.68 8517.49,3325.68 ; 5623.86,2579.76 5623.86,3450 ; 5955.86,2579.76 5955.86,3450 ; 6592.43,2579.76 6592.43,3450 ; 6851.57,2579.76 6851.57,3450 ; 7226.72,2579.76 7226.72,3450 ; 7951.05,2579.76 7951.05,3450 ; 5286,2579.76 8517.49,2579.76 8517.49,3450 5286,3450 5286,2579.76
  text "Symbol" at 5360.59,3362.98 h72
  text "Quantity" at 5661.16,3362.98 h72
  text "Finished Hole Size" at 5993.16,3362.98 h72
  text "Plated" at 6629.72,3362.98 h72
  text "Hole Type" at 6888.86,3362.98 h72
  text "Drill Layer Pair" at 7264.02,3362.98 h72
  text "Hole Tolerance" at 7988.35,3362.98 h72
  text "20" at 5661.16,3238.66 h60
  text "15.00mil (0.381mm)" at 5993.16,3238.66 h60
  text "PTH" at 6629.72,3238.66 h60
  text "Round" at 6888.86,3238.66 h60
  text "Top Layer - Bottom Layer" at 7264.02,3238.66 h60
  text "2" at 5661.16,3114.34 h60
  text "33.47mil (0.850mm)" at 5993.16,3114.34 h60
  text "PTH" at 6629.72,3114.34 h60
  text "Round" at 6888.86,3114.34 h60
  text "Top Layer - Bottom Layer" at 7264.02,3114.34 h60
  text "8" at 5661.16,2990.02 h60
  text "40.00mil (1.016mm)" at 5993.16,2990.02 h60
  text "PTH" at 6629.72,2990.02 h60
  text "Round" at 6888.86,2990.02 h60
  text "Top Layer - Bottom Layer" at 7264.02,2990.02 h60
  text "2" at 5661.16,2865.7 h60
  text "43.31mil (1.100mm)" at 5993.16,2865.7 h60
  text "PTH" at 6629.72,2865.7 h60
  text "Round" at 6888.86,2865.7 h60
  text "Top Layer - Bottom Layer" at 7264.02,2865.7 h60
  text "2" at 5661.16,2741.38 h60
  text "50.00mil (1.270mm)" at 5993.16,2741.38 h60
  text "PTH" at 6629.72,2741.38 h60
  text "Round" at 6888.86,2741.38 h60
  text "Top Layer - Bottom Layer" at 7264.02,2741.38 h60
  text "34 Total" at 5661.16,2617.06 h60
  text ".Layer_Name" at 577,-858.49 h60
M17 Embedded Cavity:
  text ".Layer_Name" at 577,-858.49 h60
M18 Embedded Assembly:
  text ".Layer_Name" at 577,-858.49 h60
M19 Embedded Keepout:
  text ".Layer_Name" at 577,-858.49 h60

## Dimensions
0,0 to 2150,0 on M2 Board Dimensions
0,0 to 0,1400 on M2 Board Dimensions
0,-400 to 1000,-400 on M2 Board Dimensions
